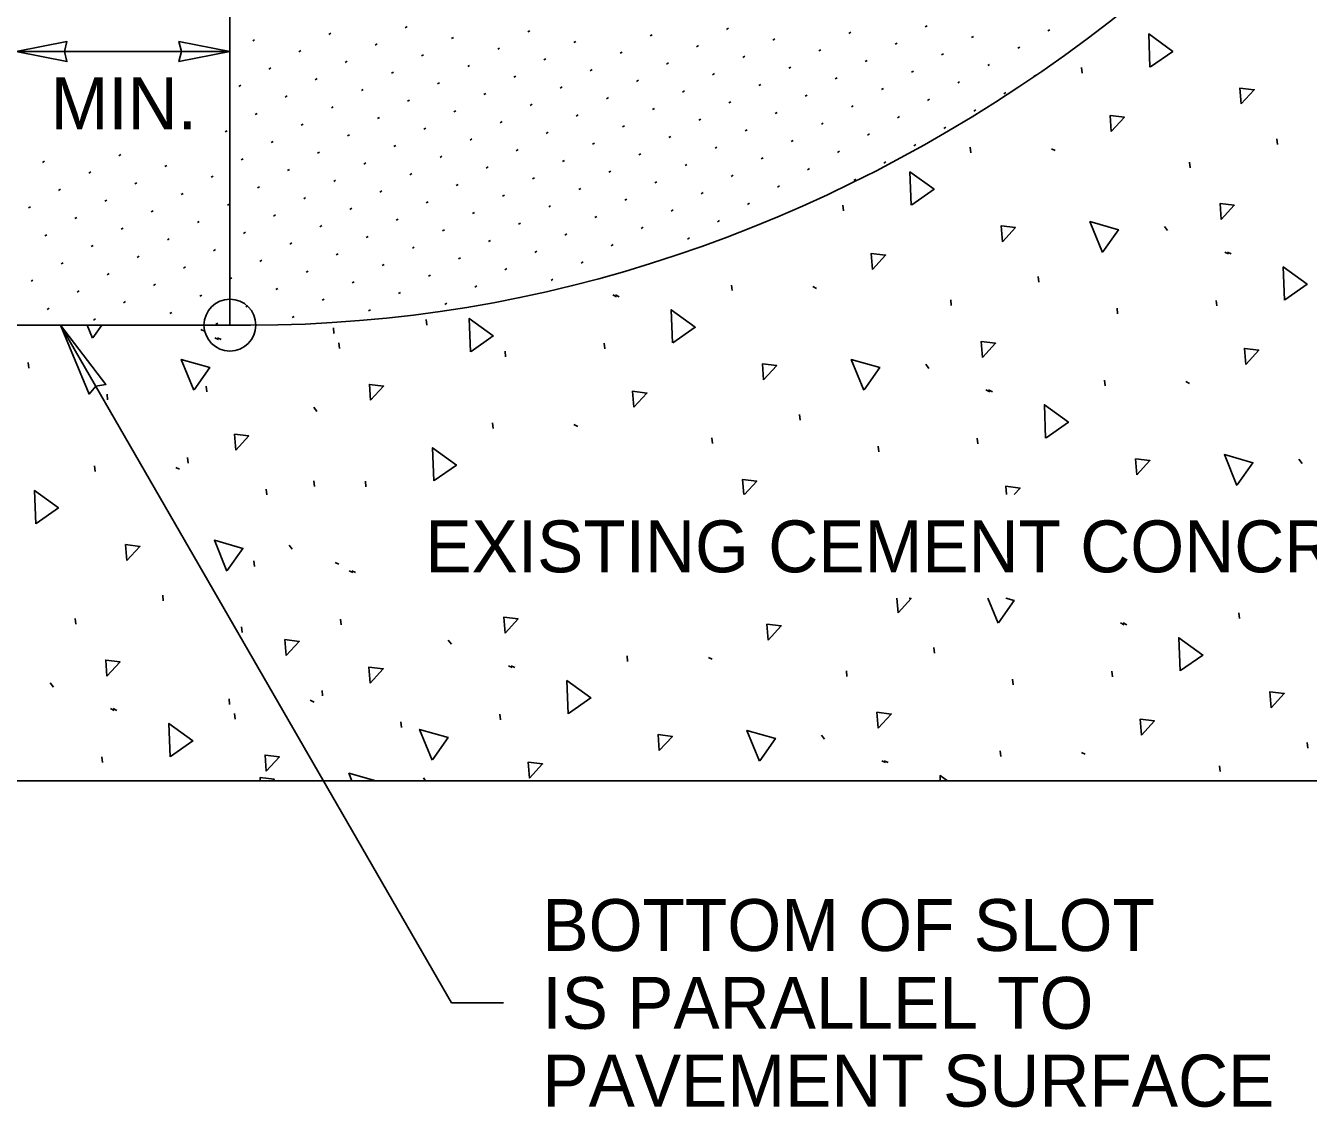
# Model space of a CAD drawing. Extents: x 99862 to 104211, y 98939 to 105076.
# Drawn here: x 101994.4 to 102390.3, y 103703.9 to 104037.6 of the extents above; entities that cross this region are included whole.
import ezdxf

# ---------------------------------------------------------------- set-up
doc = ezdxf.new("R2010")
doc.units = 0
for name, color, linetype in [('Level 1', 7, 'Continuous'), ('Level 15', 7, 'Continuous'), ('Level 20', 7, 'Continuous'), ('Level 3', 7, 'Continuous'), ('Level 4', 7, 'Continuous')]:
    doc.layers.add(name, color=color, linetype=linetype)

msp = doc.modelspace()

# ---------------------------------------------------------------- linework, layer by layer
at = {"layer": 'Level 1'}
msp.add_line((102063.85, 103945.23), (100698.76, 103945.23), dxfattribs=at)
msp.add_line((102063.85, 103945.23), (100698.76, 103945.23), dxfattribs=at)
msp.add_lwpolyline([(100169.63, 103804.62), (100694.77, 103804.62), (102647.84, 103804.62)], dxfattribs=at)
msp.add_ellipse((102063.85, 104535.63), major_axis=(0, -590.4), ratio=0.83118, start_param=0, end_param=1.074783, dxfattribs=at)
msp.add_ellipse((102063.85, 104535.63), major_axis=(0, -590.4), ratio=0.83118, start_param=0, end_param=1.074783, dxfattribs=at)
at = {"layer": 'Level 15'}
for p, q in [((102057.49, 103945.23), (102057.49, 104263.53)), ((102005.21, 103945.23), (102125.91, 103736.17)), ((102125.91, 103736.17), (102141.91, 103736.17))]:
    msp.add_line(p, q, dxfattribs=at)
for points in [[(101991.48, 104029.62), (102007.2, 104026.54), (102006.47, 104029.62), (102007.2, 104032.7)], [(102057.49, 104029.62), (102041.76, 104026.54), (102042.49, 104029.62), (102041.76, 104032.7)], [(102005.21, 103945.23), (102014.04, 103923.97), (102016.09, 103926.38), (102019.21, 103926.95)]]:
    msp.add_lwpolyline(points, close=True, dxfattribs=at)
msp.add_lwpolyline([(101991.48, 104029.62), (102057.49, 104029.62), (102057.49, 104029.62)], dxfattribs=at)
msp.add_circle((102057.47, 103945.23), 8, dxfattribs=at)
at = {"layer": 'Level 3'}
for p, q in [((102111.58, 104036.96), (102112.18, 104037.31)), ((102272.06, 104037.24), (102272.66, 104037.59)), ((102064.51, 104032.88), (102065.11, 104033.23)), ((102088.04, 104034.92), (102088.65, 104035.27)), ((102125.85, 104033.65), (102126.45, 104034)), ((102149.38, 104035.69), (102149.99, 104036.04)), ((102187.18, 104034.43), (102187.79, 104034.78)), ((102210.72, 104036.47), (102211.33, 104036.82)), ((102224.99, 104033.16), (102225.59, 104033.51)), ((102248.52, 104035.2), (102249.13, 104035.55)), ((102286.33, 104033.93), (102286.93, 104034.28)), ((102309.86, 104035.97), (102310.47, 104036.32)), ((102078.78, 104029.57), (102079.38, 104029.92)), ((102102.31, 104031.61), (102102.92, 104031.96)), ((102140.11, 104030.34), (102140.72, 104030.69)), ((102163.65, 104032.38), (102164.26, 104032.73)), ((102177.92, 104029.08), (102178.52, 104029.43)), ((102201.45, 104031.12), (102202.06, 104031.47)), ((102239.26, 104029.85), (102239.86, 104030.2)), ((102262.79, 104031.89), (102263.4, 104032.24)), ((102300.59, 104030.62), (102301.2, 104030.97)), ((102093.04, 104026.26), (102093.65, 104026.61)), ((102116.58, 104028.3), (102117.18, 104028.65)), ((102130.85, 104024.99), (102131.45, 104025.34)), ((102154.38, 104027.03), (102154.99, 104027.38)), ((102192.18, 104025.77), (102192.79, 104026.12)), ((102215.72, 104027.81), (102216.33, 104028.16)), ((102253.52, 104026.54), (102254.13, 104026.89)), ((102277.06, 104028.58), (102277.66, 104028.93)), ((102291.33, 104025.27), (102291.93, 104025.62)), ((102069.51, 104024.22), (102070.11, 104024.57)), ((102083.78, 104020.91), (102084.38, 104021.26)), ((102107.31, 104022.95), (102107.92, 104023.3)), ((102145.11, 104021.68), (102145.72, 104022.03)), ((102168.65, 104023.72), (102169.26, 104024.07)), ((102206.45, 104022.46), (102207.06, 104022.81)), ((102229.99, 104024.5), (102230.59, 104024.85)), ((102244.26, 104021.19), (102244.86, 104021.54)), ((102267.79, 104023.23), (102268.4, 104023.58)), ((102305.59, 104021.96), (102306.2, 104022.31)), ((102060.24, 104018.87), (102060.85, 104019.22)), ((102098.04, 104017.6), (102098.65, 104017.95)), ((102121.58, 104019.64), (102122.18, 104019.99)), ((102159.38, 104018.37), (102159.99, 104018.72)), ((102182.92, 104020.42), (102183.52, 104020.77)), ((102197.18, 104017.11), (102197.79, 104017.46)), ((102220.72, 104019.15), (102221.33, 104019.5)), ((102258.52, 104017.88), (102259.13, 104018.23)), ((102282.06, 104019.92), (102282.66, 104020.27)), ((102074.51, 104015.56), (102075.11, 104015.91)), ((102112.31, 104014.29), (102112.92, 104014.64)), ((102135.85, 104016.33), (102136.45, 104016.68)), ((102150.11, 104013.02), (102150.72, 104013.37)), ((102173.65, 104015.06), (102174.26, 104015.41)), ((102211.45, 104013.8), (102212.06, 104014.15)), ((102234.99, 104015.84), (102235.59, 104016.19)), ((102272.79, 104014.57), (102273.4, 104014.92)), ((102296.33, 104016.61), (102296.93, 104016.96)), ((102065.24, 104010.21), (102065.85, 104010.56)), ((102088.78, 104012.25), (102089.38, 104012.6)), ((102103.04, 104008.94), (102103.65, 104009.29)), ((102126.58, 104010.98), (102127.18, 104011.33)), ((102164.38, 104009.71), (102164.99, 104010.06)), ((102187.92, 104011.75), (102188.52, 104012.1)), ((102225.72, 104010.49), (102226.33, 104010.84)), ((102249.26, 104012.53), (102249.86, 104012.88)), ((102263.52, 104009.22), (102264.13, 104009.57)), ((102287.06, 104011.26), (102287.66, 104011.61)), ((102079.51, 104006.9), (102080.11, 104007.25)), ((102117.31, 104005.63), (102117.92, 104005.98)), ((102140.85, 104007.67), (102141.45, 104008.02)), ((102178.65, 104006.4), (102179.26, 104006.75)), ((102202.18, 104008.45), (102202.79, 104008.8)), ((102216.45, 104005.14), (102217.06, 104005.49)), ((102239.99, 104007.18), (102240.59, 104007.53)), ((102277.79, 104005.91), (102278.4, 104006.26)), ((102055.97, 104004.86), (102056.58, 104005.21)), ((102070.24, 104001.55), (102070.85, 104001.9)), ((102093.78, 104003.59), (102094.38, 104003.94)), ((102131.58, 104002.32), (102132.18, 104002.67)), ((102155.11, 104004.36), (102155.72, 104004.71)), ((102169.38, 104001.05), (102169.99, 104001.4)), ((102192.92, 104003.09), (102193.52, 104003.44)), ((102230.72, 104001.83), (102231.33, 104002.18)), ((102254.26, 104003.87), (102254.86, 104004.22)), ((102023.17, 103997.47), (102023.78, 103997.82)), ((102084.51, 103998.24), (102085.11, 103998.59)), ((102108.04, 104000.28), (102108.65, 104000.63)), ((102145.85, 103999.01), (102146.45, 103999.36)), ((102183.65, 103997.74), (102184.26, 103998.09)), ((102207.18, 103999.79), (102207.79, 104000.14)), ((102244.99, 103998.52), (102245.59, 103998.87)), ((102268.52, 104000.56), (102269.13, 104000.91)), ((101999.63, 103995.43), (102000.24, 103995.78)), ((102037.44, 103994.16), (102038.04, 103994.51)), ((102060.97, 103996.2), (102061.58, 103996.55)), ((102098.78, 103994.93), (102099.38, 103995.28)), ((102122.31, 103996.97), (102122.92, 103997.32)), ((102136.58, 103993.66), (102137.18, 103994.01)), ((102160.11, 103995.7), (102160.72, 103996.05)), ((102197.92, 103994.43), (102198.52, 103994.78)), ((102221.45, 103996.48), (102222.06, 103996.83)), ((102235.72, 103993.17), (102236.33, 103993.52)), ((102259.26, 103995.21), (102259.86, 103995.56)), ((102013.9, 103992.12), (102014.51, 103992.47)), ((102051.7, 103990.85), (102052.31, 103991.2)), ((102075.24, 103992.89), (102075.85, 103993.24)), ((102089.51, 103989.58), (102090.11, 103989.93)), ((102113.04, 103991.62), (102113.65, 103991.97)), ((102150.85, 103990.35), (102151.45, 103990.7)), ((102174.38, 103992.39), (102174.99, 103992.74)), ((102212.18, 103991.12), (102212.79, 103991.47)), ((102249.99, 103989.86), (102250.59, 103990.21)), ((102004.63, 103986.77), (102005.24, 103987.12)), ((102028.17, 103988.81), (102028.78, 103989.16)), ((102042.44, 103985.5), (102043.04, 103985.85)), ((102065.97, 103987.54), (102066.58, 103987.89)), ((102103.78, 103986.27), (102104.38, 103986.62)), ((102127.31, 103988.31), (102127.92, 103988.66)), ((102165.11, 103987.04), (102165.72, 103987.39)), ((102188.65, 103989.08), (102189.26, 103989.43)), ((102202.92, 103985.77), (102203.52, 103986.12)), ((102226.45, 103987.82), (102227.06, 103988.17)), ((101995.37, 103981.41), (101995.97, 103981.76)), ((102018.9, 103983.46), (102019.51, 103983.81)), ((102056.7, 103982.19), (102057.31, 103982.54)), ((102080.24, 103984.23), (102080.85, 103984.58)), ((102118.04, 103982.96), (102118.65, 103983.31)), ((102141.58, 103985), (102142.18, 103985.35)), ((102155.85, 103981.69), (102156.45, 103982.04)), ((102179.38, 103983.73), (102179.99, 103984.08)), ((102217.18, 103982.46), (102217.79, 103982.81)), ((102009.63, 103978.11), (102010.24, 103978.46)), ((102033.17, 103980.15), (102033.78, 103980.5)), ((102070.97, 103978.88), (102071.58, 103979.23)), ((102094.51, 103980.92), (102095.11, 103981.27)), ((102108.78, 103977.61), (102109.38, 103977.96)), ((102132.31, 103979.65), (102132.92, 103980)), ((102170.11, 103978.38), (102170.72, 103978.73)), ((102193.65, 103980.42), (102194.26, 103980.77)), ((102023.9, 103974.8), (102024.51, 103975.15)), ((102047.44, 103976.84), (102048.04, 103977.19)), ((102061.7, 103973.53), (102062.31, 103973.88)), ((102085.24, 103975.57), (102085.85, 103975.92)), ((102123.04, 103974.3), (102123.65, 103974.65)), ((102146.58, 103976.34), (102147.18, 103976.69)), ((102184.38, 103975.07), (102184.99, 103975.42)), ((102207.92, 103977.11), (102208.52, 103977.46)), ((102000.37, 103972.75), (102000.97, 103973.1)), ((102014.63, 103969.44), (102015.24, 103969.79)), ((102038.17, 103971.49), (102038.78, 103971.84)), ((102075.97, 103970.22), (102076.58, 103970.57)), ((102099.51, 103972.26), (102100.11, 103972.61)), ((102137.31, 103970.99), (102137.92, 103971.34)), ((102160.85, 103973.03), (102161.45, 103973.38)), ((102175.11, 103969.72), (102175.72, 103970.07)), ((102198.65, 103971.76), (102199.26, 103972.11)), ((102028.9, 103966.14), (102029.51, 103966.49)), ((102052.44, 103968.18), (102053.04, 103968.53)), ((102090.24, 103966.91), (102090.85, 103967.26)), ((102113.78, 103968.95), (102114.38, 103969.3)), ((102128.04, 103965.64), (102128.65, 103965.99)), ((102151.58, 103967.68), (102152.18, 103968.03)), ((102005.37, 103964.09), (102005.97, 103964.44)), ((102043.17, 103962.83), (102043.78, 103963.18)), ((102066.7, 103964.87), (102067.31, 103965.22)), ((102080.97, 103961.56), (102081.58, 103961.91)), ((102104.51, 103963.6), (102105.11, 103963.95)), ((102142.31, 103962.33), (102142.92, 103962.68)), ((102165.85, 103964.37), (102166.45, 103964.72)), ((101996.1, 103958.74), (101996.7, 103959.09)), ((102019.63, 103960.78), (102020.24, 103961.13)), ((102033.9, 103957.48), (102034.51, 103957.83)), ((102057.44, 103959.52), (102058.04, 103959.87)), ((102095.24, 103958.25), (102095.85, 103958.6)), ((102118.78, 103960.29), (102119.38, 103960.64)), ((102156.58, 103959.02), (102157.18, 103959.37)), ((102010.37, 103955.43), (102010.97, 103955.78)), ((102048.17, 103954.17), (102048.78, 103954.52)), ((102071.7, 103956.21), (102072.31, 103956.56)), ((102109.51, 103954.94), (102110.11, 103955.29)), ((102133.04, 103956.98), (102133.65, 103957.33)), ((102001.1, 103950.08), (102001.7, 103950.43)), ((102024.63, 103952.12), (102025.24, 103952.47)), ((102062.44, 103950.86), (102063.04, 103951.21)), ((102085.97, 103952.9), (102086.58, 103953.25)), ((102100.24, 103949.59), (102100.85, 103949.94)), ((102123.78, 103951.63), (102124.38, 103951.98)), ((102015.37, 103946.77), (102015.97, 103947.12)), ((102038.9, 103948.81), (102039.51, 103949.16)), ((102076.7, 103947.55), (102077.31, 103947.9)), ((102053.17, 103945.51), (102053.78, 103945.86))]:
    msp.add_line(p, q, dxfattribs=at)
at = {"layer": 'Level 4'}
for p, q in [((102320.5, 104022.98), (102320.32, 104024.72)), ((102380.79, 104000.98), (102380.6, 104002.72)), ((102286.09, 103998.4), (102285.91, 104000.14)), ((102311, 103999.66), (102312.15, 103999.09)), ((102353.77, 103993.79), (102353.58, 103995.53)), ((102246.83, 103980.45), (102246.64, 103982.19)), ((102345.91, 103975.69), (102346.86, 103974.4)), ((102364.48, 103967.78), (102365.63, 103967.21)), ((102365.3, 103967.78), (102366.45, 103967.21)), ((102307.11, 103958.44), (102306.93, 103960.18)), ((102175.64, 103954.55), (102176.79, 103953.98)), ((102176.46, 103954.55), (102177.61, 103953.99)), ((102212.42, 103955.86), (102212.23, 103957.6)), ((102237.33, 103957.12), (102238.47, 103956.55)), ((102280.09, 103951.25), (102279.91, 103952.99)), ((102331.41, 103948.68), (102331.23, 103950.42)), ((102361.99, 103951.14), (102361.8, 103952.87)), ((102118.28, 103945.22), (102118.09, 103946.96)), ((102048.49, 103943.89), (102049.64, 103943.32)), ((102089.58, 103942.64), (102089.4, 103944.38)), ((102052.81, 103941.32), (102053.96, 103940.76)), ((102053.63, 103941.33), (102054.77, 103940.76)), ((102091.26, 103938.03), (102091.07, 103939.77)), ((102173.15, 103937.91), (102172.97, 103939.65)), ((102142.57, 103935.46), (102142.39, 103937.2)), ((101995.44, 103931.99), (101995.26, 103933.73)), ((102272.23, 103933.16), (102273.19, 103931.86)), ((102050.31, 103924.68), (102050.13, 103926.42)), ((102327.58, 103926.55), (102327.39, 103928.29)), ((102352.48, 103927.81), (102353.63, 103927.24)), ((102019.74, 103922.23), (102019.55, 103923.97)), ((102290.8, 103925.24), (102291.95, 103924.67)), ((102291.62, 103925.24), (102292.77, 103924.68)), ((102083.4, 103919.93), (102084.35, 103918.63)), ((102138.74, 103913.33), (102138.56, 103915.06)), ((102163.65, 103914.58), (102164.8, 103914.01)), ((102233.43, 103915.91), (102233.25, 103917.65)), ((102206.41, 103908.72), (102206.23, 103910.46)), ((102288.31, 103908.6), (102288.12, 103910.34)), ((102257.73, 103906.15), (102257.55, 103907.89)), ((102044.6, 103902.68), (102044.41, 103904.42)), ((102387.39, 103903.85), (102388.35, 103902.55)), ((102015.9, 103900.1), (102015.72, 103901.84)), ((102040.81, 103901.35), (102041.96, 103900.79)), ((102068.9, 103892.92), (102068.71, 103894.66)), ((102083.58, 103895.49), (102083.39, 103897.23)), ((102099.47, 103895.37), (102099.29, 103897.11)), ((102075.72, 103877.39), (102076.67, 103876.1)), ((102065.06, 103870.79), (102064.88, 103872.53)), ((102089.97, 103872.04), (102091.12, 103871.48)), ((102094.29, 103869.47), (102095.44, 103868.91)), ((102095.11, 103869.48), (102096.26, 103868.91)), ((102036.92, 103860.14), (102036.74, 103861.88)), ((102369.06, 103854.7), (102368.87, 103856.44)), ((102009.9, 103852.95), (102009.72, 103854.69)), ((102061.22, 103850.38), (102061.04, 103852.12)), ((102091.8, 103852.83), (102091.61, 103854.57)), ((102332.28, 103853.39), (102333.43, 103852.82)), ((102333.1, 103853.4), (102334.25, 103852.83)), ((102124.88, 103848.08), (102125.83, 103846.79)), ((102180.22, 103841.48), (102180.04, 103843.22)), ((102274.92, 103844.06), (102274.73, 103845.8)), ((102143.45, 103840.16), (102144.6, 103839.6)), ((102144.27, 103840.17), (102145.41, 103839.6)), ((102205.13, 103842.73), (102206.28, 103842.17)), ((102247.9, 103836.87), (102247.71, 103838.61)), ((102299.21, 103834.3), (102299.03, 103836.04)), ((102329.79, 103836.75), (102329.61, 103838.49)), ((102002.04, 103834.85), (102003, 103833.56)), ((102086.08, 103830.83), (102085.9, 103832.57)), ((102057.39, 103828.25), (102057.2, 103829.99)), ((102082.29, 103829.51), (102083.44, 103828.94)), ((102020.61, 103826.94), (102021.76, 103826.37)), ((102021.43, 103826.94), (102022.58, 103826.37)), ((102059.06, 103823.64), (102058.88, 103825.38)), ((102140.95, 103823.52), (102140.77, 103825.26)), ((102110.38, 103821.07), (102110.19, 103822.81)), ((102240.04, 103818.77), (102240.99, 103817.48)), ((102390.07, 103814.75), (102389.89, 103816.49)), ((102018.12, 103810.3), (102017.93, 103812.04)), ((102295.38, 103812.17), (102295.2, 103813.91)), ((102320.29, 103813.42), (102321.44, 103812.86)), ((102258.61, 103810.85), (102259.75, 103810.29)), ((102259.42, 103810.86), (102260.57, 103810.29)), ((102363.05, 103807.56), (102362.87, 103809.3)), ((102117.2, 103805.54), (102117.88, 103804.62))]:
    msp.add_line(p, q, dxfattribs=at)
for points in [[(102341.4, 104024.8), (102341.03, 104035.04), (102348.43, 104029.67), (102341.56, 104024.89)], [(102369.53, 104013.45), (102369.15, 104018.36), (102373.56, 104017.83), (102369.53, 104013.45)], [(102329.46, 104004.98), (102329.09, 104009.89), (102333.5, 104009.36), (102329.46, 104004.98)], [(102267.73, 103982.26), (102267.35, 103992.5), (102274.76, 103987.14), (102267.88, 103982.35)], [(102363.4, 103977.82), (102363.03, 103982.73), (102367.43, 103982.2), (102363.4, 103977.82)], [(102295.85, 103970.92), (102295.48, 103975.83), (102299.88, 103975.3), (102295.85, 103970.92)], [(102326.74, 103967.66), (102322.89, 103977.15), (102331.68, 103974.64), (102326.86, 103967.79)], [(102255.79, 103962.44), (102255.41, 103967.36), (102259.82, 103966.82), (102255.79, 103962.44)], [(102382.89, 103952.95), (102382.51, 103963.19), (102389.91, 103957.83), (102383.04, 103953.04)], [(102194.05, 103939.72), (102193.67, 103949.96), (102201.08, 103944.6), (102194.2, 103939.81)], [(102131.72, 103937.04), (102131.35, 103947.28), (102138.75, 103941.92), (102131.88, 103937.13)], [(102015.07, 103941.2), (102013.43, 103945.23)], [(102017.92, 103945.23), (102015.18, 103941.34)], [(102289.72, 103935.28), (102289.35, 103940.19), (102293.76, 103939.66), (102289.72, 103935.28)], [(102370.94, 103933.13), (102370.57, 103938.04), (102374.98, 103937.51), (102370.94, 103933.13)], [(102046.31, 103925.14), (102042.46, 103934.64), (102051.25, 103932.13), (102046.43, 103925.28)], [(102253.07, 103925.12), (102249.21, 103934.61), (102258, 103932.11), (102253.18, 103925.25)], [(102222.17, 103928.38), (102221.8, 103933.29), (102226.21, 103932.76), (102222.17, 103928.38)], [(102100.89, 103922.05), (102100.51, 103926.96), (102104.92, 103926.43), (102100.89, 103922.05)], [(102182.11, 103919.91), (102181.73, 103924.82), (102186.14, 103924.29), (102182.11, 103919.91)], [(102309.21, 103910.41), (102308.83, 103920.65), (102316.24, 103915.29), (102309.36, 103910.5)], [(102059.27, 103906.68), (102058.9, 103911.59), (102063.31, 103911.06), (102059.27, 103906.68)], [(102120.37, 103897.18), (102120, 103907.43), (102127.4, 103902.06), (102120.53, 103897.27)], [(102337.33, 103899.07), (102336.96, 103903.98), (102341.37, 103903.45), (102337.33, 103899.07)], [(102368.22, 103895.81), (102364.37, 103905.3), (102373.16, 103902.8), (102368.34, 103895.94)], [(102216.03, 103892.98), (102215.67, 103897.65), (102220.08, 103897.12), (102216.27, 103892.98)], [(102297.08, 103892.98), (102296.89, 103895.51), (102301.3, 103894.98), (102299.47, 103892.98)], [(101997.54, 103883.96), (101997.16, 103894.2), (102004.57, 103888.84), (101997.69, 103884.05)], [(102056.55, 103869.35), (102052.7, 103878.85), (102061.49, 103876.34), (102056.67, 103869.49)], [(102025.66, 103872.61), (102025.29, 103877.53), (102029.69, 103876.99), (102025.66, 103872.61)], [(102263.65, 103856.53), (102263.31, 103860.98)], [(102267.07, 103860.98), (102267.69, 103860.91), (102263.65, 103856.53)], [(102294.55, 103853.27), (102291.41, 103860.98)], [(102296.93, 103860.98), (102299.48, 103860.26), (102294.66, 103853.41)], [(102142.37, 103850.21), (102141.99, 103855.12), (102146.4, 103854.59), (102142.37, 103850.21)], [(102223.59, 103848.06), (102223.21, 103852.97), (102227.62, 103852.44), (102223.59, 103848.06)], [(102074.82, 103843.3), (102074.44, 103848.21), (102078.85, 103847.68), (102074.82, 103843.3)], [(102350.69, 103838.56), (102350.31, 103848.8), (102357.72, 103843.44), (102350.84, 103838.65)], [(102019.53, 103836.98), (102019.16, 103841.89), (102023.57, 103841.36), (102019.53, 103836.98)], [(102100.75, 103834.83), (102100.38, 103839.74), (102104.79, 103839.21), (102100.75, 103834.83)], [(102161.85, 103825.34), (102161.48, 103835.58), (102168.88, 103830.21), (102162.01, 103825.43)], [(102378.81, 103827.22), (102378.44, 103832.13), (102382.85, 103831.6), (102378.81, 103827.22)], [(102257.53, 103820.9), (102257.15, 103825.81), (102261.56, 103825.27), (102257.53, 103820.9)], [(102338.75, 103818.75), (102338.37, 103823.66), (102342.78, 103823.13), (102338.75, 103818.75)], [(102039.02, 103812.11), (102038.64, 103822.35), (102046.05, 103816.99), (102039.17, 103812.2)], [(102119.86, 103811.02), (102116, 103820.52), (102124.79, 103818.01), (102119.97, 103811.16)], [(102220.87, 103810.73), (102217.01, 103820.23), (102225.81, 103817.72), (102220.98, 103810.87)], [(102189.98, 103813.99), (102189.6, 103818.9), (102194.01, 103818.37), (102189.98, 103813.99)], [(102068.69, 103807.67), (102068.32, 103812.58), (102072.73, 103812.05), (102068.69, 103807.67)], [(102149.91, 103805.52), (102149.54, 103810.43), (102153.95, 103809.9), (102149.91, 103805.52)], [(102066.85, 103804.62), (102066.77, 103805.68), (102071.18, 103805.15), (102070.69, 103804.62)], [(102095.14, 103804.62), (102094.18, 103807), (102102.52, 103804.62)], [(102276.7, 103804.62), (102276.64, 103806.27), (102278.91, 103804.62)]]:
    msp.add_lwpolyline(points, dxfattribs=at)

# ---------------------------------------------------------------- texts
at = {"layer": 'Level 20'}
for s, p in [('MIN.', (102002.15, 104005.62)), ('EXISTING CEMENT CONCRETE PAVEMENT', (102117.78, 103868.98)), ('BOTTOM OF SLOT ', (102153.91, 103752.17)), ('IS PARALLEL TO ', (102153.91, 103728.17)), ('PAVEMENT SURFACE ', (102153.91, 103704.17))]:
    msp.add_text(s, height=16, dxfattribs=at).set_placement(p)

doc.saveas('drawing.dxf')
